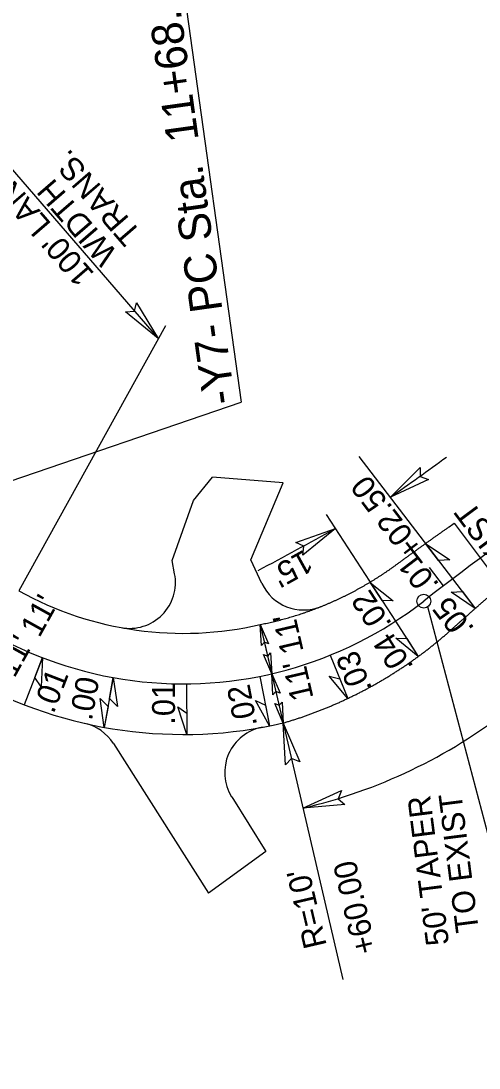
# Model space of a CAD drawing. Extents: x 472216 to 481979, y 489069 to 507339.
# Drawn here: x 478251.2 to 478350.8, y 497302.4 to 497530.3 of the extents above; entities that cross this region are included whole.
import ezdxf

# ---------------------------------------------------------------- set-up
doc = ezdxf.new("R2010")
doc.units = 0
for name, color, linetype in [('Old_Level_12', 7, 'Continuous'), ('Prop Drainage Structure Drop Inlet Grate 2 Narrow Slots and Sag Grates 840 24 CELL', 7, 'Continuous'), ('Prop Drainage Structure Drop Inlet Grate 2 Wide Slots and Sag Grates 840 22 Label', 7, 'Continuous'), ('Prop Drainage Structure Outlet Berm Ditch 850 10 CELL', 7, 'Continuous'), ('Prop Drainage Structure Pipe CSP 15in', 7, 'Continuous'), ('Prop Drainage Structure Pipe RCP 24in Class III Label', 7, 'Continuous'), ('Sheet Block Revision CELL', 7, 'Continuous'), ('Sheet North Arrow Point CELL', 7, 'Continuous'), ('Sheet PE Seal Cell', 7, 'Continuous')]:
    doc.layers.add(name, color=color, linetype=linetype)

msp = doc.modelspace()

# ---------------------------------------------------------------- linework, layer by layer
at = {"layer": 'Old_Level_12'}
for p, q in [((478283.23, 497561.27), (478299.08, 497447.35)), ((478218.63, 497419.84), (478299.08, 497447.35)), ((478366.22, 497302.45), (478339.66, 497402.82))]:
    msp.add_line(p, q, dxfattribs=at)
msp.add_circle((478338.81, 497404.05), 1.5, dxfattribs=at)
msp.add_circle((478338.81, 497404.05), 1.5, dxfattribs=at)
at = {"layer": 'Prop Drainage Structure Drop Inlet Grate 2 Narrow Slots and Sag Grates 840 24 CELL'}
for points in [[(478339.22, 497416.61), (478344.45, 497413.05), (478342.03, 497412.93)], [(478327.22, 497408.07), (478332.16, 497404.12), (478329.74, 497404.18)], [(478350.01, 497402.47), (478344.78, 497406.03), (478347.21, 497406.15)], [(478337.62, 497392.02), (478332.71, 497396), (478335.13, 497395.92)], [(478255.83, 497391.76), (478255.53, 497385.44), (478254.16, 497387.44)], [(478271.24, 497387.42), (478272.13, 497381.15), (478270.41, 497382.87)], [(478322.28, 497382.88), (478318.2, 497387.72), (478320.57, 497387.18)], [(478269.27, 497376.59), (478268.37, 497382.86), (478270.1, 497381.14)], [(478305.27, 497376.9), (478302.18, 497382.41), (478304.4, 497381.44)], [(478287.28, 497375.04), (478285.28, 497381.04), (478287.28, 497379.67)]]:
    msp.add_lwpolyline(points, close=True, dxfattribs=at)
at = {"layer": 'Prop Drainage Structure Drop Inlet Grate 2 Wide Slots and Sag Grates 840 22 Label'}
for p, q in [((478345.12, 497408.88), (478324.77, 497435.55)), ((478317.58, 497422.93), (478332.66, 497399.68)), ((478339.22, 497416.61), (478350.01, 497402.47)), ((478332.64, 497399.71), (478337.62, 497392.02)), ((478255.83, 497391.76), (478251.86, 497381.5)), ((478318.46, 497392.28), (478322.28, 497382.88)), ((478271.24, 497387.42), (478269.27, 497376.59)), ((478303.12, 497387.68), (478305.27, 497376.9)), ((478287.19, 497386.04), (478287.28, 497375.04))]:
    msp.add_line(p, q, dxfattribs=at)
for points in [[(478339.81, 497430.55), (478331.55, 497426.66), (478338.05, 497433.16), (478338.02, 497431.19)], [(478310.97, 497416.8), (478319.57, 497419.89), (478312.48, 497414.04), (478312.69, 497416)]]:
    msp.add_lwpolyline(points, close=True, dxfattribs=at)
for centre, start, end in [((477807.59, 498170.68), 305.1541, 306.09855), ((477875.84, 498214.37), 297.97927, 299.18373)]:
    msp.add_arc(centre, 910, start, end, dxfattribs=at)
at = {"layer": 'Prop Drainage Structure Outlet Berm Ditch 850 10 CELL'}
for points in [[(478276.32, 497469), (478281.03, 497461.18), (478273.9, 497466.98), (478275.87, 497467.16)], [(478303.51, 497394.4), (478303.24, 497398.96), (478305.05, 497394.73), (478304.14, 497395.11)], [(478305.47, 497392.8), (478305.73, 497388.24), (478303.93, 497392.47), (478304.84, 497392.09)], [(478306, 497383.68), (478305.73, 497388.24), (478307.54, 497384.02), (478306.63, 497384.4)], [(478307.96, 497382.09), (478308.22, 497377.53), (478306.42, 497381.76), (478307.33, 497381.38)], [(478308.75, 497368.42), (478308.22, 497377.53), (478311.83, 497369.08), (478310.01, 497369.84)], [(478321.63, 497359.78), (478312.52, 497359.03), (478320.89, 497362.84), (478320.17, 497361)]]:
    msp.add_lwpolyline(points, close=True, dxfattribs=at)
at = {"layer": 'Prop Drainage Structure Pipe CSP 15in'}
msp.add_line((478303.95, 497395.9), (478307.51, 497380.59), dxfattribs=at)
at = {"layer": 'Prop Drainage Structure Pipe RCP 24in Class III Label'}
for p, q in [((478288.73, 497425.96), (478292.8, 497431.04)), ((478308.23, 497429.79), (478292.8, 497431.04)), ((478301.2, 497413.01), (478308.23, 497429.79)), ((478284.04, 497412.91), (478288.73, 497425.96)), ((478345.43, 497421.01), (478355.63, 497407.35)), ((478284.6, 497410.02), (478284.04, 497412.91)), ((478303.6, 497407.89), (478301.2, 497413.01)), ((478271.26, 497373.08), (478291.94, 497340.53)), ((478297.01, 497361.47), (478304.42, 497349.58)), ((478304.42, 497349.58), (478291.94, 497340.53))]:
    msp.add_line(p, q, dxfattribs=at)
for centre, radius, start, end in [((478274.78, 497408.12), 10, 259.4694, 10.9481), ((478312.65, 497412.13), 10, 205.0819, 291.7664), ((478286.48, 497471.04), 74, 241.0713, 283.0917), ((478286.48, 497471.04), 96, 241.0713, 283.0917), ((478262.82, 497367.71), 10, 32.4361, 77.1029), ((478305.49, 497366.76), 10, 100.3336, 211.923)]:
    msp.add_arc(centre, radius, start, end, dxfattribs=at)
for points in [[(478303.24, 497398.96), (478303.86, 497399.09), (478304.47, 497399.22), (478305.09, 497399.35), (478305.7, 497399.49), (478306.32, 497399.64), (478306.93, 497399.79), (478307.54, 497399.94), (478308.15, 497400.11), (478308.76, 497400.27), (478309.36, 497400.44), (478309.97, 497400.62), (478310.57, 497400.8), (478311.18, 497400.99), (478311.78, 497401.18), (478312.38, 497401.38), (478312.98, 497401.59), (478313.57, 497401.79), (478314.17, 497402.01), (478314.76, 497402.23), (478315.35, 497402.45), (478315.94, 497402.68), (478316.53, 497402.91), (478317.12, 497403.15), (478317.7, 497403.39), (478318.29, 497403.64), (478318.87, 497403.9), (478319.45, 497404.16), (478320.02, 497404.42), (478320.6, 497404.69), (478321.17, 497404.96), (478321.74, 497405.24), (478322.31, 497405.52), (478322.87, 497405.81), (478323.44, 497406.11), (478324, 497406.4), (478324.56, 497406.71), (478325.11, 497407.02), (478325.67, 497407.33), (478326.22, 497407.65), (478326.76, 497407.97), (478327.31, 497408.3), (478327.85, 497408.63), (478328.39, 497408.96), (478328.93, 497409.31), (478329.47, 497409.65), (478330, 497410), (478330.53, 497410.36), (478331.06, 497410.72), (478331.58, 497411.08), (478332.1, 497411.45), (478332.62, 497411.82), (478333.17, 497412.22), (478333.72, 497412.63), (478334.27, 497413.03), (478334.83, 497413.44), (478335.38, 497413.84), (478335.94, 497414.24), (478336.49, 497414.65), (478337.05, 497415.05), (478337.61, 497415.45), (478338.16, 497415.85), (478338.72, 497416.25), (478339.28, 497416.65), (478339.84, 497417.05), (478340.39, 497417.45), (478340.95, 497417.84), (478341.51, 497418.24), (478342.07, 497418.64), (478342.63, 497419.03), (478343.19, 497419.43), (478343.75, 497419.82), (478344.31, 497420.22), (478345.43, 497421.01)], [(478308.22, 497377.53), (478309.01, 497377.77), (478309.79, 497378.01), (478310.57, 497378.25), (478311.34, 497378.5), (478312.12, 497378.76), (478312.89, 497379.03), (478313.65, 497379.3), (478314.42, 497379.58), (478315.18, 497379.86), (478315.94, 497380.15), (478316.7, 497380.45), (478317.45, 497380.76), (478318.2, 497381.06), (478318.95, 497381.38), (478319.69, 497381.7), (478320.44, 497382.03), (478321.17, 497382.37), (478321.91, 497382.71), (478322.64, 497383.05), (478323.37, 497383.41), (478324.1, 497383.77), (478324.82, 497384.13), (478325.54, 497384.5), (478326.25, 497384.88), (478326.96, 497385.26), (478327.67, 497385.65), (478328.37, 497386.04), (478329.07, 497386.44), (478329.77, 497386.85), (478330.46, 497387.26), (478331.15, 497387.68), (478331.83, 497388.1), (478332.52, 497388.53), (478333.19, 497388.97), (478333.86, 497389.41), (478334.53, 497389.85), (478335.2, 497390.3), (478335.86, 497390.76), (478336.51, 497391.22), (478337.17, 497391.69), (478337.81, 497392.16), (478338.46, 497392.64), (478339.09, 497393.12), (478339.73, 497393.61), (478340.36, 497394.1), (478340.98, 497394.6), (478341.6, 497395.1), (478342.22, 497395.61), (478342.83, 497396.12), (478343.44, 497396.64), (478344.04, 497397.16), (478344.55, 497397.62), (478345.05, 497398.07), (478345.55, 497398.52), (478346.05, 497398.96), (478346.55, 497399.41), (478347.05, 497399.85), (478347.55, 497400.3), (478348.05, 497400.74), (478348.56, 497401.18), (478349.06, 497401.63), (478349.56, 497402.07), (478350.06, 497402.51), (478350.57, 497402.95), (478351.07, 497403.4), (478351.58, 497403.84), (478352.08, 497404.28), (478352.59, 497404.72), (478353.09, 497405.16), (478353.6, 497405.6), (478354.11, 497406.04), (478354.61, 497406.47), (478355.63, 497407.35)]]:
    msp.add_spline(points, degree=3, dxfattribs=at)
at = {"layer": 'Sheet Block Revision CELL'}
for p, q in [((478234.36, 497515.2), (478281.03, 497461.18)), ((478282.59, 497463.99), (478250.68, 497406.27)), ((478303.24, 497398.96), (478308.23, 497377.53)), ((478308.22, 497377.53), (478321.21, 497321.7))]:
    msp.add_line(p, q, dxfattribs=at)
msp.add_arc((478286.48, 497471.04), 115, 283.0916, 307.9978, dxfattribs=at)
at = {"layer": 'Sheet North Arrow Point CELL'}
for centre, radius, start, end in [((478772.83, 496848.49), 705, 121.40298, 127.99777), ((478286.48, 497471.04), 85, 217.0354, 307.9978)]:
    msp.add_arc(centre, radius, start, end, dxfattribs=at)
at = {"layer": 'Sheet PE Seal Cell'}
msp.add_line((478343.11, 497407.39), (478340.06, 497411.35), dxfattribs=at)

# ---------------------------------------------------------------- texts
at = {"layer": 'Old_Level_12'}
msp.add_text('-Y7- PC Sta.  11+68.34', height=7, rotation=97.9227, dxfattribs=at).set_placement((478297.82, 497447.27))
at = {"layer": 'Prop Drainage Structure Drop Inlet Grate 2 Narrow Slots and Sag Grates 840 24 CELL'}
for s, rotation, p in [('EXIST', 126.742, (478360.79, 497410.7)), ('.01', 127.352, (478342.34, 497407.68)), ('.02', 122.9687, (478332.02, 497399.1)), ('.05', 127.515, (478349.98, 497398.11)), ('.04', 122.2958, (478336.71, 497389.78)), ('.03', 111.4862, (478327.61, 497385.01)), ('.01', 68.8614, (478258.26, 497379.4)), ('.00', 79.671, (478266.58, 497377.91)), ('.01', 89.8671, (478284.68, 497377.17)), ('.02', 100.6766, (478302.58, 497377.09))]:
    msp.add_text(s, height=5, rotation=rotation, dxfattribs=at).set_placement(p)
at = {"layer": 'Prop Drainage Structure Drop Inlet Grate 2 Wide Slots and Sag Grates 840 22 Label'}
for s, rotation, p in [('+02.50', 127.352, (478339.09, 497415.44)), ("15'", 209.0172, (478312.82, 497415.39))]:
    msp.add_text(s, height=5, rotation=rotation, dxfattribs=at).set_placement(p)
at = {"layer": 'Prop Drainage Structure Pipe CSP 15in'}
for s, rotation, p in [('TRANS.', 130.8218, (478277.56, 497484.18)), ("100' LANE", 130.8218, (478267.29, 497475.31)), ('WIDTH ', 130.8218, (478272.42, 497479.75)), ("11'", 61.0713, (478255.16, 497395.92)), ("11'", 103.0881, (478312.7, 497393.19)), ("11'", 61.0713, (478249.74, 497387.15)), ("11'", 103.0881, (478314.85, 497383.01)), ("50' TAPER", 97.2747, (478344.33, 497329.42)), ('TO EXIST', 97.2747, (478350.81, 497332.27)), ('+60.00', 103.0911, (478328.57, 497327.86)), ("R=10'", 103.0911, (478317.72, 497329.13))]:
    msp.add_text(s, height=5, rotation=rotation, dxfattribs=at).set_placement(p)

doc.saveas('drawing.dxf')
